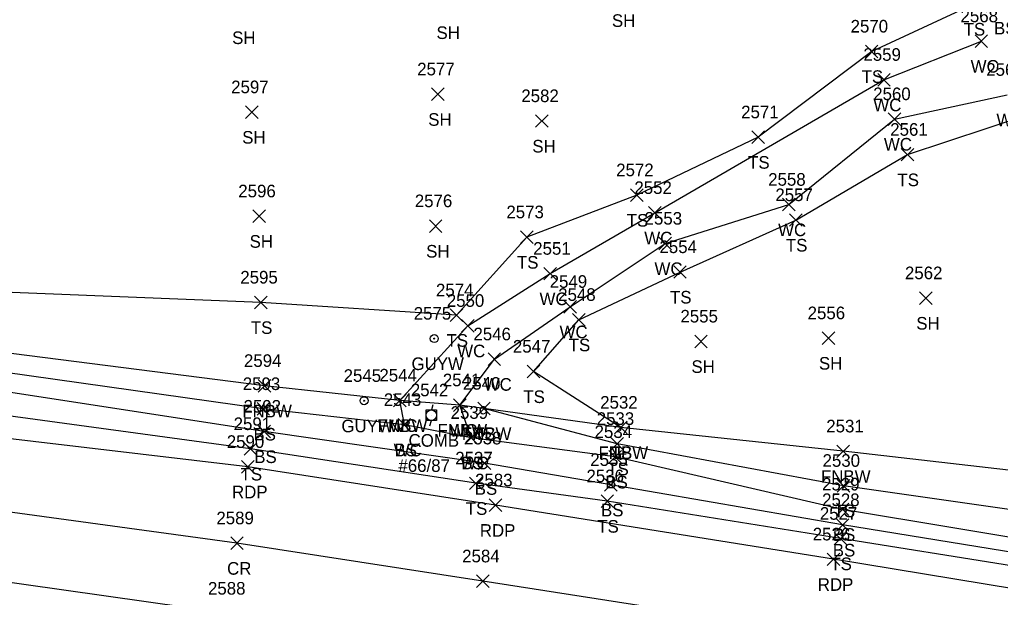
# Model space of a CAD drawing. Extents: x 1443590 to 1445966, y 578314 to 580556.
# Drawn here: x 1444767.8 to 1444923.5, y 579121.5 to 579213.2 of the extents above; entities that cross this region are included whole.
import ezdxf

# ---------------------------------------------------------------- set-up
doc = ezdxf.new("R2010")
doc.units = 0
for name, color, linetype in [('L_A', 7, 'Continuous'), ('L_I', 7, 'Continuous'), ('L_TIC', 7, 'Continuous'), ('LAWE', 7, 'Continuous'), ('LELB', 7, 'Continuous'), ('LFNC', 7, 'Continuous'), ('P_A', 7, 'Continuous'), ('P_I', 7, 'Continuous'), ('P_TIC', 7, 'Continuous'), ('PET', 7, 'Continuous'), ('PRC', 7, 'Continuous'), ('U_A', 7, 'Continuous'), ('U_C', 7, 'Continuous'), ('U_I', 7, 'Continuous'), ('UP', 7, 'Continuous'), ('UPGW', 7, 'Continuous')]:
    doc.layers.add(name, color=color, linetype=linetype)

msp = doc.modelspace()

# ---------------------------------------------------------------- linework, layer by layer
at = {"layer": 'L_TIC'}
for points in [[(1444919.46, 579208.74), (1444921.46, 579210.74)], [(1444921.46, 579208.74), (1444919.46, 579210.74)], [(1444902.05, 579207.11), (1444904.05, 579209.11)], [(1444904.05, 579207.11), (1444902.05, 579209.11)], [(1444904, 579202.62), (1444906, 579204.62)], [(1444906, 579202.62), (1444904, 579204.62)], [(1444833.16, 579200.31), (1444835.16, 579202.31)], [(1444835.16, 579200.31), (1444833.16, 579202.31)], [(1444803.63, 579197.48), (1444805.63, 579199.48)], [(1444805.63, 579197.48), (1444803.63, 579199.48)], [(1444849.69, 579196.07), (1444851.69, 579198.07)], [(1444851.69, 579196.07), (1444849.69, 579198.07)], [(1444905.68, 579196.38), (1444907.68, 579198.38)], [(1444907.68, 579196.38), (1444905.68, 579198.38)], [(1444884.02, 579193.5), (1444886.02, 579195.5)], [(1444886.02, 579193.5), (1444884.02, 579195.5)], [(1444907.73, 579190.73), (1444909.73, 579192.73)], [(1444909.73, 579190.73), (1444907.73, 579192.73)], [(1444864.75, 579184.31), (1444866.75, 579186.31)], [(1444866.75, 579184.31), (1444864.75, 579186.31)], [(1444888.88, 579182.8), (1444890.88, 579184.8)], [(1444890.88, 579182.8), (1444888.88, 579184.8)], [(1444804.81, 579180.96), (1444806.81, 579182.96)], [(1444806.81, 579180.96), (1444804.81, 579182.96)], [(1444867.64, 579181.49), (1444869.64, 579183.49)], [(1444869.64, 579181.49), (1444867.64, 579183.49)], [(1444890.02, 579180.36), (1444892.02, 579182.36)], [(1444892.02, 579180.36), (1444890.02, 579182.36)], [(1444832.83, 579179.4), (1444834.83, 579181.4)], [(1444834.83, 579179.4), (1444832.83, 579181.4)], [(1444847.32, 579177.64), (1444849.32, 579179.64)], [(1444849.32, 579177.64), (1444847.32, 579179.64)], [(1444869.26, 579176.63), (1444871.26, 579178.63)], [(1444871.26, 579176.63), (1444869.26, 579178.63)], [(1444851.01, 579171.85), (1444853.01, 579173.85)], [(1444853.01, 579171.85), (1444851.01, 579173.85)], [(1444871.62, 579172.11), (1444873.62, 579174.11)], [(1444873.62, 579172.11), (1444871.62, 579174.11)], [(1444910.64, 579167.97), (1444912.64, 579169.97)], [(1444912.64, 579167.97), (1444910.64, 579169.97)], [(1444805.08, 579167.28), (1444807.08, 579169.28)], [(1444807.08, 579167.28), (1444805.08, 579169.28)], [(1444854.2, 579166.6), (1444856.2, 579168.6)], [(1444856.2, 579166.6), (1444854.2, 579168.6)], [(1444836.14, 579165.25), (1444838.14, 579167.25)], [(1444838.14, 579165.25), (1444836.14, 579167.25)], [(1444855.54, 579164.53), (1444857.54, 579166.53)], [(1444857.54, 579164.53), (1444855.54, 579166.53)], [(1444837.94, 579163.58), (1444839.94, 579165.58)], [(1444839.94, 579163.58), (1444837.94, 579165.58)], [(1444895.2, 579161.62), (1444897.2, 579163.62)], [(1444897.2, 579161.62), (1444895.2, 579163.62)], [(1444874.95, 579161.1), (1444876.95, 579163.1)], [(1444876.95, 579161.1), (1444874.95, 579163.1)], [(1444842.15, 579158.27), (1444844.15, 579160.27)], [(1444844.15, 579158.27), (1444842.15, 579160.27)], [(1444848.35, 579156.32), (1444850.35, 579158.32)], [(1444850.35, 579156.32), (1444848.35, 579158.32)], [(1444805.66, 579154.05), (1444807.66, 579156.05)], [(1444807.66, 579154.05), (1444805.66, 579156.05)], [(1444805.47, 579150.38), (1444807.47, 579152.38)], [(1444807.47, 579150.38), (1444805.47, 579152.38)], [(1444827.16, 579151.74), (1444829.16, 579153.74)], [(1444829.16, 579151.74), (1444827.16, 579153.74)], [(1444827.16, 579151.74), (1444829.16, 579153.74)], [(1444829.16, 579151.74), (1444827.16, 579153.74)], [(1444836.66, 579150.98), (1444838.66, 579152.98)], [(1444838.66, 579150.98), (1444836.66, 579152.98)], [(1444836.66, 579150.98), (1444838.66, 579152.98)], [(1444838.66, 579150.98), (1444836.66, 579152.98)], [(1444840.5, 579150.44), (1444842.5, 579152.44)], [(1444842.5, 579150.44), (1444840.5, 579152.44)], [(1444840.5, 579150.44), (1444842.5, 579152.44)], [(1444842.5, 579150.44), (1444840.5, 579152.44)], [(1444827.86, 579147.86), (1444829.86, 579149.86)], [(1444829.86, 579147.86), (1444827.86, 579149.86)], [(1444827.86, 579147.86), (1444829.86, 579149.86)], [(1444829.86, 579147.86), (1444827.86, 579149.86)], [(1444862.21, 579147.43), (1444864.21, 579149.43)], [(1444864.21, 579147.43), (1444862.21, 579149.43)], [(1444862.21, 579147.43), (1444864.21, 579149.43)], [(1444864.21, 579147.43), (1444862.21, 579149.43)], [(1444805.59, 579146.8), (1444807.59, 579148.8)], [(1444807.59, 579146.8), (1444805.59, 579148.8)], [(1444838.47, 579145.81), (1444840.47, 579147.81)], [(1444840.47, 579145.81), (1444838.47, 579147.81)], [(1444838.47, 579145.81), (1444840.47, 579147.81)], [(1444840.47, 579145.81), (1444838.47, 579147.81)], [(1444861.66, 579144.85), (1444863.66, 579146.85)], [(1444863.66, 579144.85), (1444861.66, 579146.85)], [(1444803.45, 579144.03), (1444805.45, 579146.03)], [(1444805.45, 579144.03), (1444803.45, 579146.03)], [(1444861.32, 579142.77), (1444863.32, 579144.77)], [(1444863.32, 579142.77), (1444861.32, 579144.77)], [(1444897.53, 579143.66), (1444899.53, 579145.66)], [(1444899.53, 579143.66), (1444897.53, 579145.66)], [(1444840.59, 579141.76), (1444842.59, 579143.76)], [(1444842.59, 579141.76), (1444840.59, 579143.76)], [(1444839.2, 579138.58), (1444841.2, 579140.58)], [(1444841.2, 579138.58), (1444839.2, 579140.58)], [(1444860.64, 579138.34), (1444862.64, 579140.34)], [(1444862.64, 579138.34), (1444860.64, 579140.34)], [(1444897.59, 579138.2), (1444899.59, 579140.2)], [(1444899.59, 579138.2), (1444897.59, 579140.2)], [(1444860.08, 579135.75), (1444862.08, 579137.75)], [(1444862.08, 579135.75), (1444860.08, 579137.75)], [(1444897.44, 579134.45), (1444899.44, 579136.45)], [(1444899.44, 579134.45), (1444897.44, 579136.45)], [(1444897.44, 579131.97), (1444899.44, 579133.97)], [(1444899.44, 579131.97), (1444897.44, 579133.97)], [(1444897.08, 579129.8), (1444899.08, 579131.8)], [(1444899.08, 579129.8), (1444897.08, 579131.8)]]:
    msp.add_lwpolyline(points, dxfattribs=at)
at = {"layer": 'LAWE'}
for points in [[(1444828.86, 579148.86), (1444828.16, 579152.74), (1444838.94, 579164.58), (1444852.01, 579172.85), (1444868.64, 579182.49), (1444905, 579203.62), (1444920.46, 579209.74)], [(1444839.47, 579146.81), (1444837.66, 579151.98), (1444843.15, 579159.27), (1444855.2, 579167.6), (1444870.26, 579177.63), (1444889.88, 579183.8), (1444906.68, 579197.38), (1444924.54, 579201.24)]]:
    msp.add_lwpolyline(points, dxfattribs=at)
at = {"layer": 'LELB'}
for points in [[(1444960.57, 579355.06), (1444979.05, 579324.01), (1445003.21, 579286.86), (1445017.62, 579260.88), (1445040.92, 579227.07), (1445056.02, 579202.79), (1445077.14, 579169.23), (1445087.88, 579152.95), (1445100.68, 579131.75), (1445100.63, 579124.41), (1445093.66, 579121.61), (1445094.66, 579118.69), (1445096.17, 579112.31), (1445078.21, 579111.11), (1445047.27, 579111.15), (1445003.8, 579115.46), (1444971.29, 579119.24), (1444952.39, 579122.15), (1444898.08, 579130.8), (1444861.08, 579136.75), (1444840.2, 579139.58), (1444804.45, 579145.03), (1444761.25, 579150.91)], [(1444919.24, 579215.63), (1444903.05, 579208.11), (1444885.02, 579194.5), (1444865.75, 579185.31), (1444848.32, 579178.64), (1444837.14, 579166.25), (1444806.08, 579168.28), (1444761.27, 579170.06), (1444728.49, 579174.89), (1444695.59, 579190.16), (1444696.54, 579181.03), (1444600.23, 579193.23), (1444579.91, 579197.07)], [(1444863.21, 579148.43), (1444849.35, 579157.32), (1444856.54, 579165.53), (1444872.62, 579173.11), (1444891.02, 579181.36), (1444908.73, 579191.73), (1444927.95, 579198.08)], [(1444952.22, 579126.5), (1444951.83, 579124.34), (1444898.44, 579132.97), (1444861.64, 579139.34), (1444841.59, 579142.76), (1444806.59, 579147.8), (1444760.83, 579154.84), (1444735.93, 579159.38), (1444732.05, 579162.31), (1444725.72, 579163.44), (1444718.26, 579161.73)], [(1444952.22, 579126.5), (1444898.44, 579135.45), (1444862.32, 579143.77), (1444839.47, 579146.81), (1444828.86, 579148.86), (1444806.47, 579151.38), (1444760.97, 579157.82), (1444736.4, 579164.07)], [(1444954.44, 579131.19), (1444898.59, 579139.2), (1444862.66, 579145.85), (1444841.5, 579151.44)]]:
    msp.add_lwpolyline(points, dxfattribs=at)
at = {"layer": 'LFNC'}
msp.add_lwpolyline([(1444955.6, 579138.13), (1444898.53, 579144.66), (1444863.21, 579148.43), (1444841.5, 579151.44), (1444837.66, 579151.98), (1444828.16, 579152.74), (1444806.66, 579155.05), (1444761.42, 579160.79), (1444736.4, 579164.07), (1444732.18, 579164.69), (1444726.63, 579166.18), (1444714, 579169.84), (1444695.54, 579173.36), (1444651.38, 579183.34), (1444642.72, 579186.31), (1444620.68, 579181.6), (1444610.9, 579179.65), (1444587.6, 579174.08), (1444560.1, 579167.55), (1444546.27, 579164.71)], dxfattribs=at)
at = {"layer": 'P_TIC'}
for points in [[(1444803.01, 579141.2), (1444805.01, 579143.2)], [(1444805.01, 579141.2), (1444803.01, 579143.2)], [(1444842.35, 579135.1), (1444844.35, 579137.1)], [(1444844.35, 579135.1), (1444842.35, 579137.1)], [(1444801.29, 579129.08), (1444803.29, 579131.08)], [(1444803.29, 579129.08), (1444801.29, 579131.08)], [(1444896, 579126.52), (1444898, 579128.52)], [(1444898, 579126.52), (1444896, 579128.52)], [(1444840.3, 579123.04), (1444842.3, 579125.04)], [(1444842.3, 579123.04), (1444840.3, 579125.04)]]:
    msp.add_lwpolyline(points, dxfattribs=at)
at = {"layer": 'PET'}
for points in [[(1445134.69, 579101.81), (1445094.76, 579101.93), (1445077.63, 579103.26), (1445047.47, 579105.53), (1445003.1, 579110.32), (1444971.83, 579115.27), (1444949.98, 579118.8), (1444897, 579127.52), (1444843.35, 579136.1), (1444804.01, 579142.2), (1444761.37, 579147.22), (1444731.36, 579149.89), (1444695.84, 579152.24), (1444655.33, 579151.42), (1444615.59, 579148.93), (1444572.86, 579141.4), (1444535.21, 579131.29)], [(1445142.74, 579080.19), (1445099.09, 579079.55), (1445065.12, 579082.68), (1445030.26, 579085.35), (1445022.74, 579086.17), (1444988.69, 579090.02), (1444959.19, 579093.88), (1444932.36, 579098.94), (1444909.91, 579101.57), (1444895.06, 579103.61), (1444854.36, 579109.97), (1444841.37, 579112.53), (1444800.95, 579118.92), (1444761.66, 579124.5), (1444731.12, 579127.67), (1444695.07, 579130.45), (1444655.65, 579130.52), (1444618.8, 579127.98), (1444577.17, 579120.56), (1444542.16, 579111.25)]]:
    msp.add_lwpolyline(points, dxfattribs=at)
at = {"layer": 'PRC'}
msp.add_lwpolyline([(1445133.82, 579090.86), (1445081.89, 579091.59), (1445046.45, 579094.38), (1445002.6, 579099.63), (1444971.23, 579104.03), (1444941.6, 579108.7), (1444896.29, 579115.49), (1444841.3, 579124.04), (1444802.29, 579130.08), (1444761.59, 579135.64), (1444731.75, 579138.78), (1444695.41, 579141.57), (1444655.99, 579141.27), (1444617.36, 579138.71), (1444575.01, 579131.71), (1444538.16, 579121.71)], dxfattribs=at)
at = {"layer": 'UP'}
for p, q in [((1444832.31, 579149.56), (1444832.31, 579151.22)), ((1444832.31, 579151.22), (1444833.98, 579151.22)), ((1444833.4, 579152.06), (1444833.15, 579151.22)), ((1444833.98, 579151.22), (1444833.98, 579149.56)), ((1444833.98, 579149.56), (1444832.31, 579149.56)), ((1444832.9, 579148.72), (1444833.15, 579149.56)), ((1444833.15, 579150.39), (1444833.15, 579150.39))]:
    msp.add_line(p, q, dxfattribs=at)
msp.add_circle((1444833.15, 579150.39), 0.833, dxfattribs=at)
at = {"layer": 'UPGW'}
for centre, radius in [((1444833.61, 579162.55), 0.625), ((1444833.61, 579162.55), 0.0833), ((1444822.47, 579152.68), 0.625), ((1444822.47, 579152.68), 0.0833)]:
    msp.add_circle(centre, radius, dxfattribs=at)

# ---------------------------------------------------------------- texts
at = {"layer": 'L_A'}
for s, p in [('SH', (1444861.81, 579212)), ('SH', (1444833.96, 579210.08)), ('TS', (1444917.65, 579210.63)), ('BS', (1444922.47, 579210.8)), ('SH', (1444801.52, 579209.28)), ('WC', (1444918.76, 579204.74)), ('TS', (1444901.45, 579203.11)), ('WC', (1444903.31, 579198.62)), ('SH', (1444832.65, 579196.31)), ('WC', (1444922.85, 579196.24)), ('SH', (1444803.12, 579193.48)), ('SH', (1444849.18, 579192.07)), ('WC', (1444904.99, 579192.38)), ('TS', (1444883.43, 579189.5)), ('TS', (1444907.14, 579186.73)), ('TS', (1444864.16, 579180.31)), ('WC', (1444888.19, 579178.8)), ('SH', (1444804.3, 579176.96)), ('WC', (1444866.95, 579177.49)), ('SH', (1444832.32, 579175.4)), ('TS', (1444889.43, 579176.36)), ('TS', (1444846.73, 579173.64)), ('WC', (1444868.57, 579172.63)), ('WC', (1444850.32, 579167.85)), ('TS', (1444871.03, 579168.11)), ('TS', (1444804.49, 579163.28)), ('SH', (1444910.13, 579163.97)), ('TS', (1444835.55, 579161.25)), ('WC', (1444853.5, 579162.6)), ('TS', (1444854.95, 579160.53)), ('WC', (1444837.25, 579159.58)), ('SH', (1444874.44, 579157.1)), ('SH', (1444894.68, 579157.62)), ('WC', (1444841.46, 579154.27)), ('TS', (1444847.75, 579152.32)), ('FNBW', (1444803.13, 579150.05)), ('FNBW', (1444824.64, 579147.74)), ('WC', (1444826.47, 579147.74)), ('BS', (1444804.91, 579146.38)), ('FNBW', (1444834.13, 579146.98)), ('WC', (1444835.97, 579146.98)), ('FNBW', (1444837.98, 579146.44)), ('TS', (1444839.91, 579146.44)), ('BS', (1444805.03, 579142.8)), ('WC', (1444827.17, 579143.86)), ('BS', (1444827.3, 579143.86)), ('FNBW', (1444859.68, 579143.43)), ('TS', (1444861.62, 579143.43)), ('WC', (1444837.77, 579141.81)), ('BS', (1444837.91, 579141.81)), ('TS', (1444802.86, 579140.03)), ('TS', (1444861.07, 579140.85)), ('FNBW', (1444895, 579139.66)), ('BS', (1444860.76, 579138.77)), ('BS', (1444840.03, 579137.76)), ('TS', (1444838.61, 579134.58)), ('BS', (1444860.08, 579134.34)), ('TS', (1444897, 579134.2)), ('TS', (1444859.49, 579131.75)), ('BS', (1444896.88, 579130.45)), ('BS', (1444896.88, 579127.97)), ('TS', (1444896.49, 579125.8))]:
    msp.add_text(s, height=2, dxfattribs=at).set_placement(p)
at = {"layer": 'L_I'}
for s, p in [('2568', (1444917.15, 579212.74)), ('2570', (1444899.7, 579211.11)), ('2559', (1444901.74, 579206.62)), ('2577', (1444830.9, 579204.31)), ('2567', (1444921.24, 579204.24)), ('2597', (1444801.37, 579201.48)), ('2560', (1444903.29, 579200.38)), ('2582', (1444847.43, 579200.07)), ('2571', (1444882.33, 579197.5)), ('2561', (1444905.99, 579194.73)), ('2572', (1444862.49, 579188.31)), ('2558', (1444886.62, 579186.8)), ('2596', (1444802.5, 579184.96)), ('2552', (1444865.38, 579185.49)), ('2576', (1444830.52, 579183.4)), ('2557', (1444887.76, 579184.36)), ('2573', (1444845.06, 579181.64)), ('2553', (1444867, 579180.63)), ('2551', (1444849.32, 579175.85)), ('2554', (1444869.36, 579176.11)), ('2595', (1444802.82, 579171.28)), ('2549', (1444851.93, 579170.6)), ('2562', (1444908.33, 579171.97)), ('2574', (1444833.88, 579169.25)), ('2550', (1444835.6, 579167.58)), ('2548', (1444853.28, 579168.53)), ('2555', (1444872.69, 579165.1)), ('2556', (1444892.88, 579165.62)), ('2546', (1444839.83, 579162.27)), ('2547', (1444846.09, 579160.32)), ('2594', (1444803.4, 579158.05)), ('2544', (1444824.9, 579155.74)), ('2544', (1444824.9, 579155.74)), ('2593', (1444803.21, 579154.38)), ('2541', (1444834.97, 579154.98)), ('2541', (1444834.97, 579154.98)), ('2540', (1444838.16, 579154.44)), ('2540', (1444838.16, 579154.44)), ('2592', (1444803.33, 579150.8)), ('2543', (1444825.6, 579151.86)), ('2543', (1444825.6, 579151.86)), ('2532', (1444859.95, 579151.43)), ('2532', (1444859.95, 579151.43)), ('2539', (1444836.2, 579149.81)), ('2539', (1444836.2, 579149.81)), ('2533', (1444859.4, 579148.85)), ('2591', (1444801.76, 579148.03)), ('2531', (1444895.84, 579147.66)), ('2538', (1444838.33, 579145.76)), ('2534', (1444859.06, 579146.77)), ('2537', (1444836.94, 579142.58)), ('2535', (1444858.38, 579142.34)), ('2530', (1444895.25, 579142.2)), ('2536', (1444857.77, 579139.75)), ('2529', (1444895.17, 579138.45)), ('2528', (1444895.18, 579135.97)), ('2527', (1444894.82, 579133.8))]:
    msp.add_text(s, height=2, dxfattribs=at).set_placement(p)
at = {"layer": 'P_A'}
for s, p in [('RDP', (1444801.5, 579137.2)), ('RDP', (1444840.84, 579131.1)), ('CR', (1444800.72, 579125.08)), ('RDP', (1444894.49, 579122.52))]:
    msp.add_text(s, height=2, dxfattribs=at).set_placement(p)
at = {"layer": 'P_I'}
for s, p in [('2590', (1444800.67, 579145.2)), ('2583', (1444840.09, 579139.1)), ('2589', (1444799.02, 579133.08)), ('2526', (1444893.69, 579130.52)), ('2584', (1444838.04, 579127.04)), ('2588', (1444797.69, 579121.92))]:
    msp.add_text(s, height=2, dxfattribs=at).set_placement(p)
at = {"layer": 'U_A'}
for s, p in [('GUYW', (1444830, 579157.55)), ('GUYW', (1444818.87, 579147.68)), ('COMB', (1444829.53, 579145.39))]:
    msp.add_text(s, height=2, dxfattribs=at).set_placement(p)
at = {"layer": 'U_C'}
msp.add_text('#66/87', height=2, dxfattribs=at).set_placement((1444827.92, 579141.39))
at = {"layer": 'U_I'}
for s, p in [('2575', (1444830.35, 579165.55)), ('2545', (1444819.22, 579155.68)), ('2542', (1444829.89, 579153.39))]:
    msp.add_text(s, height=2, dxfattribs=at).set_placement(p)

doc.saveas('drawing.dxf')
